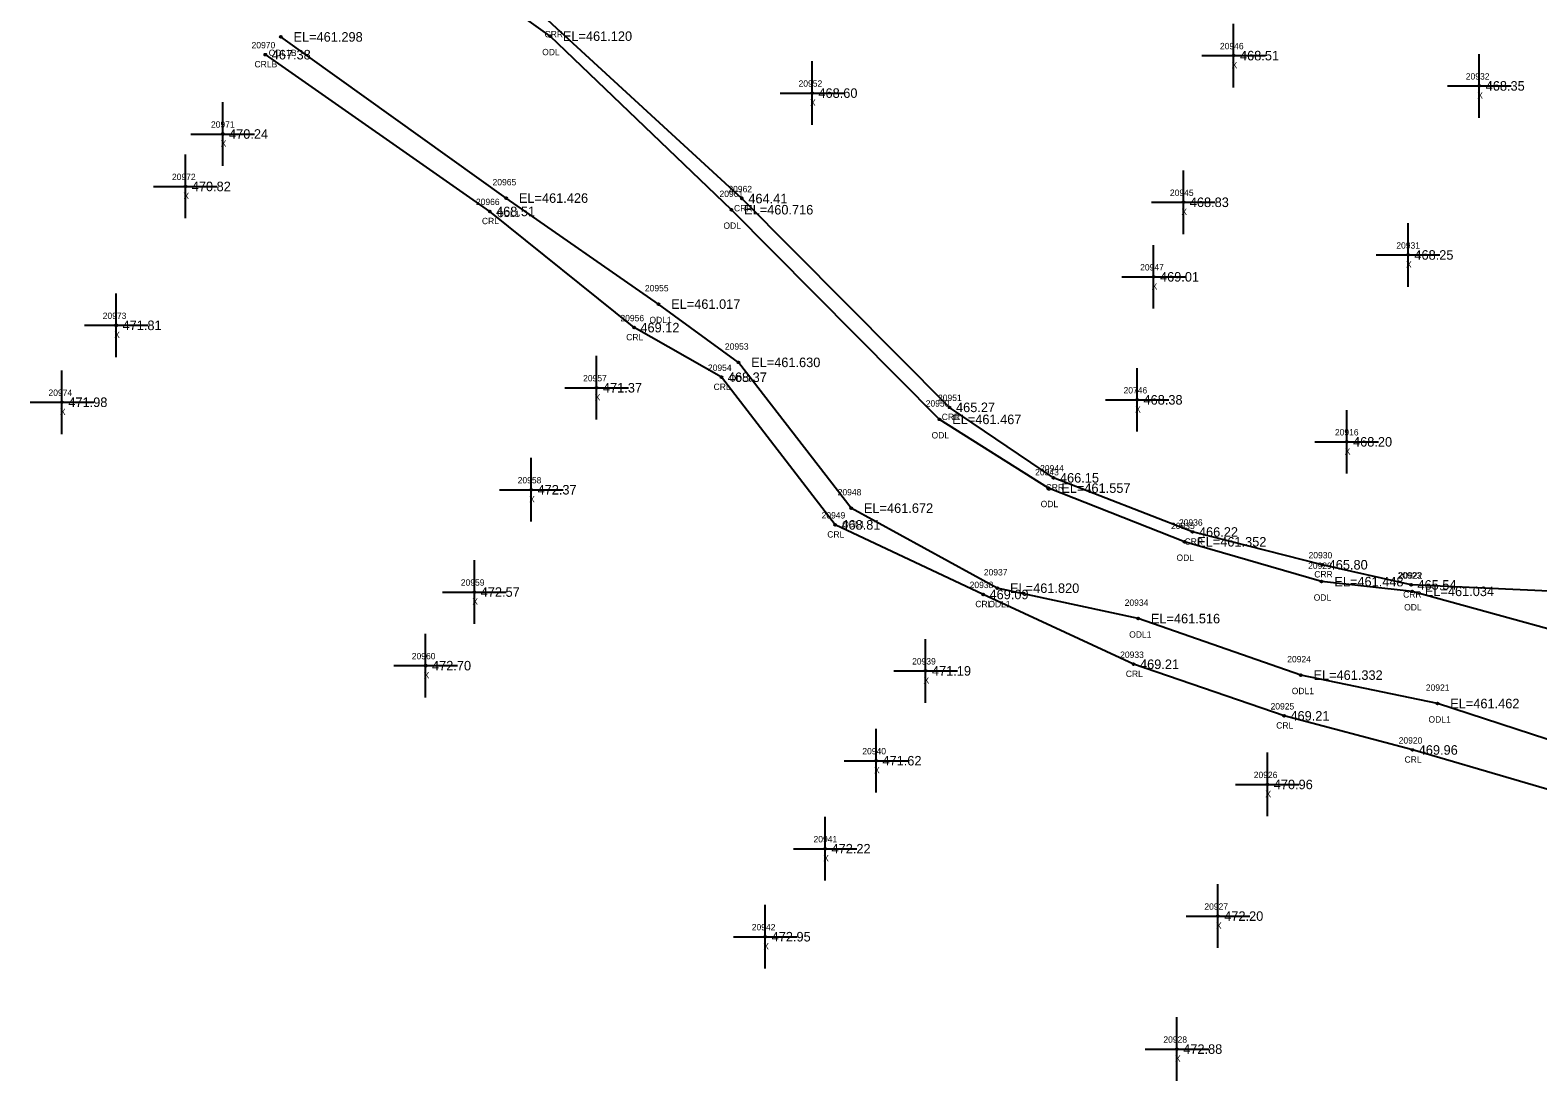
# Model space of a CAD drawing. Extents: x 1741010 to 1742139, y 749382 to 750625.
# Drawn here: x 1741009.6 to 1741246.5, y 750085.9 to 750251.1 of the extents above; entities that cross this region are included whole.
import ezdxf

# ---------------------------------------------------------------- set-up
doc = ezdxf.new("R2010")
doc.units = 0
for name, color, linetype in [('RD_EX_H2O', 7, 'Continuous'), ('RD_EX_H2O_txCode', 7, 'Continuous'), ('RD_EX_Misc', 7, 'Continuous'), ('RD_EX_Misc_txCode', 7, 'Continuous'), ('RD_EX_TX_H2O_ELEV', 7, 'Continuous'), ('RD_EX_TX_Misc_ELEV', 7, 'Continuous'), ('RD_SMD_Locator', 7, 'Continuous')]:
    doc.layers.add(name, color=color, linetype=linetype)

msp = doc.modelspace()

# ---------------------------------------------------------------- linework, layer by layer
at = {"layer": 'RD_EX_H2O'}
for points in [[(1741531.4, 750163.48), (1741496.74, 750161.28), (1741466.68, 750164.86), (1741447.36, 750172.02), (1741386.3, 750192.01), (1741353.76, 750217.14), (1741329.62, 750224.53), (1741303.91, 750221.92), (1741291.61, 750196.83), (1741282.64, 750163.36), (1741273.67, 750156.83), (1741266.54, 750162.04), (1741226.59, 750163.86), (1741212.64, 750167.03), (1741192.26, 750172.18), (1741170.42, 750180.69), (1741154.09, 750191.77), (1741121.46, 750224.58), (1741091.69, 750251.93), (1741067.74, 750274.52)], [(1741529.44, 750151.69), (1741495.88, 750157.28), (1741465.36, 750157.67), (1741446.42, 750166.61), (1741384.48, 750187.47), (1741350.45, 750210.87), (1741329.18, 750218), (1741305.86, 750217.64), (1741298.92, 750196.11), (1741302.53, 750181.39), (1741301.05, 750174.92), (1741291.08, 750166.14), (1741279.91, 750156.54), (1741273.82, 750151.82), (1741263.7, 750152.66), (1741226.75, 750162.85), (1741212.53, 750164.38), (1741190.98, 750170.64), (1741169.63, 750179.08), (1741152.49, 750189.88), (1741119.79, 750222.83), (1741091.32, 750250.11), (1741061.1, 750271.73)], [(1741257.86, 750136.37), (1741230.74, 750145.22), (1741209.25, 750149.69), (1741183.71, 750158.57), (1741161.58, 750163.35), (1741138.62, 750175.93), (1741120.9, 750198.84), (1741108.33, 750208), (1741084.41, 750224.66), (1741048.99, 750249.99)], [(1741292.06, 750123.32), (1741273.28, 750125.79), (1741260.44, 750128.09), (1741226.79, 750137.92), (1741206.63, 750143.28), (1741183, 750151.39), (1741159.35, 750162.36), (1741136.08, 750173.3), (1741118.23, 750196.5), (1741104.5, 750204.3), (1741081.82, 750222.56), (1741046.57, 750247.2)]]:
    msp.add_lwpolyline(points, dxfattribs=at)
at = {"layer": 'RD_EX_Misc'}
for p, q in [((1741198.71, 750242.05), (1741198.71, 750252.05)), ((1741193.71, 750247.05), (1741203.71, 750247.05)), ((1741237.31, 750237.29), (1741237.31, 750247.29)), ((1741132.47, 750236.16), (1741132.47, 750246.16)), ((1741232.31, 750242.29), (1741242.31, 750242.29)), ((1741039.87, 750229.73), (1741039.87, 750239.73)), ((1741127.47, 750241.16), (1741137.47, 750241.16)), ((1741034.87, 750234.73), (1741044.87, 750234.73)), ((1741034.01, 750221.49), (1741034.01, 750231.49)), ((1741190.82, 750219), (1741190.82, 750229)), ((1741029.01, 750226.49), (1741039.01, 750226.49)), ((1741185.82, 750224), (1741195.82, 750224)), ((1741226.11, 750210.72), (1741226.11, 750220.72)), ((1741186.14, 750207.28), (1741186.14, 750217.28)), ((1741221.11, 750215.72), (1741231.11, 750215.72)), ((1741181.14, 750212.28), (1741191.14, 750212.28)), ((1741023.14, 750199.66), (1741023.14, 750209.66)), ((1741018.14, 750204.66), (1741028.14, 750204.66)), ((1741098.62, 750189.85), (1741098.62, 750199.85)), ((1741014.62, 750187.57), (1741014.62, 750197.57)), ((1741183.55, 750187.95), (1741183.55, 750197.95)), ((1741093.62, 750194.85), (1741103.62, 750194.85)), ((1741009.62, 750192.57), (1741019.62, 750192.57)), ((1741178.55, 750192.95), (1741188.55, 750192.95)), ((1741216.47, 750181.35), (1741216.47, 750191.35)), ((1741211.47, 750186.35), (1741221.47, 750186.35)), ((1741088.34, 750173.82), (1741088.34, 750183.82)), ((1741083.34, 750178.82), (1741093.34, 750178.82)), ((1741079.41, 750157.74), (1741079.41, 750167.74)), ((1741074.41, 750162.74), (1741084.41, 750162.74)), ((1741071.76, 750146.17), (1741071.76, 750156.17)), ((1741150.31, 750145.35), (1741150.31, 750155.35)), ((1741066.76, 750151.17), (1741076.76, 750151.17)), ((1741145.31, 750150.35), (1741155.31, 750150.35)), ((1741142.53, 750131.23), (1741142.53, 750141.23)), ((1741137.53, 750136.23), (1741147.53, 750136.23)), ((1741204.01, 750127.5), (1741204.01, 750137.5)), ((1741199.01, 750132.5), (1741209.01, 750132.5)), ((1741134.53, 750117.4), (1741134.53, 750127.4)), ((1741129.53, 750122.4), (1741139.53, 750122.4)), ((1741196.23, 750106.81), (1741196.23, 750116.81)), ((1741125.12, 750103.57), (1741125.12, 750113.57)), ((1741191.23, 750111.81), (1741201.23, 750111.81)), ((1741120.12, 750108.57), (1741130.12, 750108.57)), ((1741189.79, 750085.91), (1741189.79, 750095.91)), ((1741184.79, 750090.91), (1741194.79, 750090.91))]:
    msp.add_line(p, q, dxfattribs=at)
at = {"layer": 'RD_SMD_Locator'}
for centre in [(1741048.99, 750249.99), (1741091.32, 750250.11), (1741046.57, 750247.2), (1741198.71, 750247.05), (1741237.31, 750242.29), (1741132.47, 750241.16), (1741039.87, 750234.73), (1741034.01, 750226.49), (1741084.41, 750224.66), (1741119.79, 750222.83), (1741121.46, 750224.58), (1741190.82, 750224), (1741081.82, 750222.56), (1741226.11, 750215.72), (1741186.14, 750212.28), (1741108.33, 750208), (1741023.14, 750204.66), (1741104.5, 750204.3), (1741120.9, 750198.84), (1741098.62, 750194.85), (1741118.23, 750196.5), (1741014.62, 750192.57), (1741183.55, 750192.95), (1741152.49, 750189.88), (1741154.09, 750191.77), (1741216.47, 750186.35), (1741170.42, 750180.69), (1741088.34, 750178.82), (1741169.63, 750179.08), (1741138.62, 750175.93), (1741136.08, 750173.3), (1741190.98, 750170.64), (1741192.26, 750172.18), (1741212.64, 750167.03), (1741212.53, 750164.38), (1741226.59, 750163.86), (1741079.41, 750162.74), (1741159.35, 750162.36), (1741161.58, 750163.35), (1741226.75, 750162.85), (1741183.71, 750158.57), (1741071.76, 750151.17), (1741150.31, 750150.35), (1741183, 750151.39), (1741209.25, 750149.69), (1741230.74, 750145.22), (1741206.63, 750143.28), (1741226.79, 750137.92), (1741142.53, 750136.23), (1741204.01, 750132.5), (1741134.53, 750122.4), (1741196.23, 750111.81), (1741125.12, 750108.57), (1741189.79, 750090.91)]:
    msp.add_circle(centre, 0.15, dxfattribs=at)

# ---------------------------------------------------------------- texts
at = {"layer": 'RD_EX_H2O_txCode'}
for s, p in [('20970', (1741044.41, 750248.2)), ('CRR', (1741090.44, 750249.93)), ('ODL1B', (1741047.1, 750246.99)), ('ODL', (1741090.07, 750247.11)), ('CRLB', (1741044.87, 750245.2)), ('20965', (1741082.27, 750226.66)), ('20961', (1741117.93, 750224.83)), ('20962', (1741119.32, 750225.58)), ('20966', (1741079.66, 750223.56)), ('CRR', (1741120.21, 750222.58)), ('CRL', (1741080.6, 750220.56)), ('ODL1', (1741083, 750221.66)), ('ODL', (1741118.55, 750219.83)), ('20955', (1741106.21, 750210)), ('20956', (1741102.36, 750205.3)), ('ODL1', (1741106.92, 750205)), ('CRL', (1741103.27, 750202.3)), ('20953', (1741118.78, 750200.84)), ('20954', (1741116.11, 750197.5)), ('ODL1', (1741119.49, 750195.84)), ('CRL', (1741117, 750194.5)), ('20950', (1741150.33, 750191.88)), ('20951', (1741152.26, 750192.77)), ('CRR', (1741152.84, 750189.77)), ('ODL', (1741151.25, 750186.88)), ('20944', (1741168.3, 750181.69)), ('20943', (1741167.52, 750181.08)), ('20948', (1741136.5, 750177.93)), ('CRR', (1741169.17, 750178.69)), ('ODL', (1741168.39, 750176.08)), ('20949', (1741133.97, 750174.3)), ('ODL1', (1741137.21, 750172.93)), ('20935', (1741188.87, 750172.64)), ('20936', (1741190.12, 750173.18)), ('CRL', (1741134.86, 750171.3)), ('CRR', (1741191, 750170.18)), ('ODL', (1741189.74, 750167.64)), ('20930', (1741210.48, 750168.03)), ('20937', (1741159.46, 750165.35)), ('20929', (1741210.41, 750166.38)), ('CRR', (1741211.38, 750165.03)), ('20938', (1741157.23, 750163.36)), ('20923', (1741224.48, 750164.86)), ('20922', (1741224.63, 750164.85)), ('CRL', (1741158.12, 750160.36)), ('ODL1', (1741160.17, 750160.35)), ('20934', (1741181.59, 750160.57)), ('ODL', (1741211.29, 750161.38)), ('CRR', (1741225.34, 750161.86)), ('ODL', (1741225.5, 750159.85)), ('ODL1', (1741182.3, 750155.57)), ('20933', (1741180.88, 750152.39)), ('20924', (1741207.13, 750151.69)), ('CRL', (1741181.77, 750149.39)), ('ODL1', (1741207.84, 750146.69)), ('20921', (1741228.91, 750147.22)), ('20925', (1741204.51, 750144.28)), ('CRL', (1741205.4, 750141.28)), ('ODL1', (1741229.33, 750142.22)), ('20920', (1741224.64, 750138.92)), ('CRL', (1741225.56, 750135.92))]:
    msp.add_text(s, height=1, dxfattribs=at).set_placement(p)
at = {"layer": 'RD_EX_Misc_txCode'}
for s, p in [('20946', (1741196.56, 750248.05)), ('X', (1741198.39, 750245.05)), ('20932', (1741235.19, 750243.29)), ('20952', (1741130.35, 750242.16)), ('X', (1741132.15, 750239.16)), ('X', (1741236.99, 750240.29)), ('20971', (1741038.03, 750235.73)), ('X', (1741039.55, 750232.73)), ('20972', (1741031.9, 750227.49)), ('X', (1741033.7, 750224.49)), ('20945', (1741188.7, 750225)), ('X', (1741190.5, 750222)), ('20931', (1741224.27, 750216.72)), ('20947', (1741184.02, 750213.28)), ('X', (1741225.79, 750213.72)), ('X', (1741185.83, 750210.28)), ('20973', (1741021.02, 750205.66)), ('X', (1741022.82, 750202.66)), ('20957', (1741096.5, 750195.85)), ('20974', (1741012.5, 750193.57)), ('20746', (1741181.41, 750193.95)), ('X', (1741098.31, 750192.85)), ('X', (1741014.3, 750190.57)), ('X', (1741183.23, 750190.95)), ('20916', (1741214.62, 750187.35)), ('X', (1741216.16, 750184.35)), ('20958', (1741086.22, 750179.82)), ('X', (1741088.02, 750176.82)), ('20959', (1741077.29, 750163.74)), ('X', (1741079.09, 750160.74)), ('20960', (1741069.58, 750152.17)), ('20939', (1741148.19, 750151.35)), ('X', (1741071.44, 750149.17)), ('X', (1741149.99, 750148.35)), ('20940', (1741140.37, 750137.23)), ('X', (1741142.22, 750134.23)), ('20926', (1741201.87, 750133.5)), ('X', (1741203.7, 750130.5)), ('20941', (1741132.7, 750123.4)), ('X', (1741134.22, 750120.4)), ('20927', (1741194.11, 750112.81)), ('20942', (1741123, 750109.57)), ('X', (1741195.92, 750109.81)), ('X', (1741124.8, 750106.57)), ('20928', (1741187.67, 750091.91)), ('X', (1741189.48, 750088.91))]:
    msp.add_text(s, height=1, dxfattribs=at).set_placement(p)
at = {"layer": 'RD_EX_TX_H2O_ELEV'}
for s, p in [('EL=461.298', (1741050.99, 750249.24)), ('EL=461.120', (1741093.32, 750249.36)), ('467.38', (1741047.57, 750246.45)), ('EL=461.426', (1741086.41, 750223.91)), ('464.41', (1741122.46, 750223.83)), ('468.51', (1741082.82, 750221.81)), ('EL=460.716', (1741121.79, 750222.08)), ('EL=461.017', (1741110.33, 750207.25)), ('469.12', (1741105.5, 750203.55)), ('EL=461.630', (1741122.9, 750198.09)), ('468.37', (1741119.23, 750195.75)), ('465.27', (1741155.09, 750191.02)), ('EL=461.467', (1741154.49, 750189.13)), ('466.15', (1741171.42, 750179.94)), ('EL=461.557', (1741171.63, 750178.33)), ('EL=461.672', (1741140.62, 750175.18)), ('468.81', (1741137.08, 750172.55)), ('EL=461.352', (1741192.98, 750169.89)), ('466.22', (1741193.26, 750171.43)), ('465.80', (1741213.64, 750166.28)), ('EL=461.820', (1741163.58, 750162.6)), ('EL=461.448', (1741214.53, 750163.63)), ('465.54', (1741227.59, 750163.11)), ('EL=461.034', (1741228.75, 750162.1)), ('469.09', (1741160.35, 750161.61)), ('EL=461.516', (1741185.71, 750157.82)), ('469.21', (1741184, 750150.64)), ('EL=461.332', (1741211.25, 750148.94)), ('EL=461.462', (1741232.74, 750144.47)), ('469.21', (1741207.63, 750142.53)), ('469.96', (1741227.79, 750137.17))]:
    msp.add_text(s, height=1.5, dxfattribs=at).set_placement(p)
at = {"layer": 'RD_EX_TX_Misc_ELEV'}
for s, p in [('468.51', (1741199.71, 750246.3)), ('468.60', (1741133.47, 750240.41)), ('468.35', (1741238.31, 750241.54)), ('470.24', (1741040.87, 750233.98)), ('470.82', (1741035.01, 750225.74)), ('468.83', (1741191.82, 750223.25)), ('468.25', (1741227.11, 750214.97)), ('469.01', (1741187.14, 750211.53)), ('471.81', (1741024.14, 750203.91)), ('471.37', (1741099.62, 750194.1)), ('471.98', (1741015.62, 750191.82)), ('468.38', (1741184.55, 750192.2)), ('468.20', (1741217.47, 750185.6)), ('472.37', (1741089.34, 750178.07)), ('472.57', (1741080.41, 750161.99)), ('472.70', (1741072.76, 750150.42)), ('471.19', (1741151.31, 750149.6)), ('471.62', (1741143.53, 750135.48)), ('470.96', (1741205.01, 750131.75)), ('472.22', (1741135.53, 750121.65)), ('472.20', (1741197.23, 750111.06)), ('472.95', (1741126.12, 750107.82)), ('472.88', (1741190.79, 750090.16))]:
    msp.add_text(s, height=1.5, dxfattribs=at).set_placement(p)

doc.saveas('drawing.dxf')
